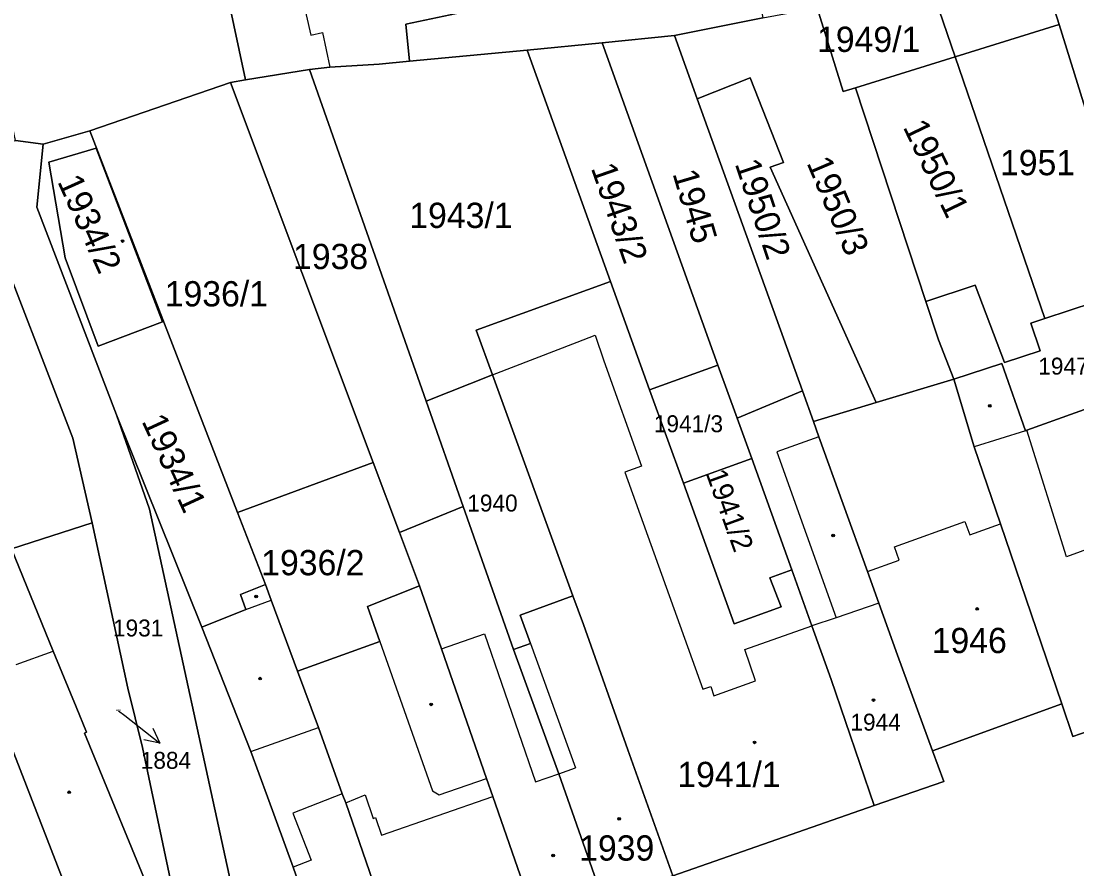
# Model space of a CAD drawing. Extents: x -596233 to -595156, y -1161235 to -1159375.
# Drawn here: x -595806.5 to -595735.4, y -1161105.5 to -1161048.4 of the extents above; entities that cross this region are included whole.
import ezdxf

# ---------------------------------------------------------------- set-up
doc = ezdxf.new("R2010")
doc.units = 0
for name, color, linetype in [('KN_CAR_KR', 7, 'Continuous'), ('KN_KULTURY', 7, 'Continuous'), ('KN_PARC_CIS_POM', 7, 'Continuous'), ('KN_PARC_CIS_POZ', 7, 'Continuous'), ('KN_PARC_CIS_STAV', 7, 'Continuous'), ('KN_PARC_PLOCHA', 7, 'Continuous'), ('PARC_C_SIPKA', 7, 'Continuous'), ('parcely_l', 7, 'Continuous')]:
    doc.layers.add(name, color=color, linetype=linetype)

msp = doc.modelspace()

# ---------------------------------------------------------------- linework, layer by layer
at = {"layer": 'KN_CAR_KR'}
for points in [[(-595788.64, -1161041.96), (-595786.95, -1161049.32)], [(-595786.95, -1161049.32), (-595786.17, -1161049.15)], [(-595786.17, -1161049.15), (-595785.67, -1161051.48)], [(-595774.72, -1161072.19), (-595769.01, -1161069.99)], [(-595769.01, -1161069.99), (-595767.8, -1161069.52)], [(-595767.8, -1161069.52), (-595767.22, -1161071.25)], [(-595767.22, -1161071.25), (-595764.67, -1161078.34)], [(-595752.73, -1161076.37), (-595755.57, -1161077.39)], [(-595738.83, -1161075.96), (-595742.28, -1161077.04)], [(-595736.05, -1161084.45), (-595738.73, -1161075.93)], [(-595755.57, -1161077.39), (-595751.57, -1161088.55)], [(-595764.67, -1161078.34), (-595765.8, -1161078.74)], [(-595765.8, -1161078.74), (-595760.56, -1161093.36)], [(-595747.65, -1161083.78), (-595742.9, -1161082.08)], [(-595742.9, -1161082.08), (-595742.58, -1161082.97)], [(-595729.38, -1161082.01), (-595736.05, -1161084.45)], [(-595742.58, -1161082.97), (-595740.51, -1161082.23)], [(-595747.33, -1161084.68), (-595747.65, -1161083.78)], [(-595749.45, -1161085.44), (-595747.33, -1161084.68)], [(-595791.33, -1161087.99), (-595789.62, -1161087.36)], [(-595748.7, -1161087.56), (-595751.57, -1161088.55)], [(-595757.71, -1161090.69), (-595753.2, -1161089.1)], [(-595751.57, -1161088.55), (-595753.2, -1161089.1)], [(-595778.14, -1161090.64), (-595775.26, -1161089.63)], [(-595775.26, -1161089.63), (-595771.81, -1161099.59)], [(-595782.3, -1161090.16), (-595778.76, -1161100.2)], [(-595772.16, -1161090.28), (-595769.12, -1161098.66)], [(-595806.8, -1161091.7), (-595804.29, -1161090.8)], [(-595757, -1161092.79), (-595757.71, -1161090.69)], [(-595760.56, -1161093.36), (-595760.02, -1161093.17)], [(-595760.02, -1161093.17), (-595759.8, -1161093.81)], [(-595759.8, -1161093.81), (-595757, -1161092.79)], [(-595790.99, -1161097.55), (-595786.43, -1161095.95)], [(-595771.81, -1161099.59), (-595770.25, -1161099.05)], [(-595770.25, -1161099.05), (-595769.12, -1161098.66)], [(-595778.3, -1161100.48), (-595775.11, -1161099.37)], [(-595784.83, -1161100.41), (-595788.16, -1161101.71)], [(-595784.59, -1161101), (-595783.29, -1161100.48)], [(-595783.29, -1161100.48), (-595782.76, -1161102.06)], [(-595778.76, -1161100.2), (-595778.3, -1161100.48)], [(-595782.19, -1161103.19), (-595774.69, -1161100.59)], [(-595788.16, -1161101.71), (-595786.93, -1161104.88)], [(-595782.76, -1161102.06), (-595782.59, -1161102)], [(-595782.59, -1161102), (-595782.19, -1161103.19)], [(-595786.93, -1161104.88), (-595788.14, -1161105.35)]]:
    msp.add_lwpolyline(points, dxfattribs=at)
at = {"layer": 'KN_KULTURY'}
for centre, radius in [((-595799.62, -1161063.19), 0.09), ((-595799.62, -1161063.19), 0.0398), ((-595741.23, -1161074.29), 0.09), ((-595741.23, -1161074.29), 0.0398), ((-595751.77, -1161083.02), 0.09), ((-595751.77, -1161083.02), 0.0398), ((-595790.63, -1161087.12), 0.09), ((-595790.63, -1161087.12), 0.0398), ((-595742.07, -1161087.96), 0.09), ((-595742.07, -1161087.96), 0.0398), ((-595790.37, -1161092.65), 0.09), ((-595790.37, -1161092.65), 0.0398), ((-595749.06, -1161094.09), 0.09), ((-595749.06, -1161094.09), 0.0398), ((-595778.84, -1161094.38), 0.09), ((-595778.84, -1161094.38), 0.0398), ((-595757.06, -1161096.94), 0.09), ((-595757.06, -1161096.94), 0.0398), ((-595803.22, -1161100.3), 0.09), ((-595803.22, -1161100.3), 0.0398), ((-595766.19, -1161102.09), 0.09), ((-595766.19, -1161102.09), 0.0398), ((-595770.63, -1161104.55), 0.09), ((-595770.63, -1161104.55), 0.0398)]:
    msp.add_circle(centre, radius, dxfattribs=at)
at = {"layer": 'KN_PARC_PLOCHA'}
for points in [[(-595800.84, -1161007.79), (-595797.39, -1161024.01), (-595795.85, -1161031.24), (-595794.6, -1161037.1), (-595793.35, -1161042.96), (-595791.35, -1161052.34), (-595792.36, -1161052.52), (-595801.84, -1161055.76), (-595804.98, -1161056.66), (-595806.83, -1161056.42), (-595808.05, -1161050.74), (-595809.17, -1161045.43), (-595810.29, -1161040.1), (-595811.82, -1161032.84), (-595812.42, -1161029.86), (-595813.02, -1161026.89), (-595816.25, -1161010.92)], [(-595807.91, -1161121.82), (-595798.85, -1161118.51), (-595794.32, -1161116.86), (-595790.25, -1161115.45), (-595785.2, -1161113.74), (-595780.74, -1161112.21), (-595771.72, -1161109.12), (-595767.26, -1161107.57), (-595762.56, -1161105.93), (-595749.01, -1161101.2), (-595744.33, -1161099.57), (-595745.08, -1161097.51), (-595736.38, -1161094.34), (-595735.63, -1161096.54), (-595722.22, -1161091.87)]]:
    msp.add_lwpolyline(points, dxfattribs=at)
for points in [[(-595756.52, -1161048.16), (-595762.45, -1161049.35), (-595767.32, -1161049.84), (-595772.39, -1161050.35), (-595780.31, -1161051.09), (-595780.54, -1161048.59), (-595774.15, -1161047.25), (-595769.47, -1161046.26), (-595771.18, -1161038.24), (-595759.1, -1161035.67)], [(-595780.31, -1161051.09), (-595782.34, -1161051.28), (-595785.67, -1161051.48), (-595787.03, -1161051.65), (-595791.35, -1161052.34), (-595793.35, -1161042.96), (-595788.64, -1161041.96), (-595778.17, -1161039.73), (-595776.02, -1161039.27), (-595775.04, -1161039.06), (-595771.18, -1161038.24), (-595769.47, -1161046.26), (-595774.15, -1161047.25), (-595780.54, -1161048.59)], [(-595726.93, -1161054.01), (-595734.08, -1161056.56), (-595736.56, -1161048.61), (-595738.25, -1161043.22), (-595735.43, -1161042.27), (-595731.29, -1161041.19), (-595730.52, -1161043.46)], [(-595736.56, -1161048.61), (-595743.56, -1161050.78), (-595745.45, -1161045.26), (-595742.24, -1161044.34), (-595738.25, -1161043.22)], [(-595743.56, -1161050.78), (-595750.27, -1161052.87), (-595751.09, -1161053.12), (-595752.84, -1161047.48), (-595752.12, -1161047.27), (-595749.08, -1161046.3), (-595745.45, -1161045.26)], [(-595750.27, -1161052.87), (-595745.53, -1161067.27), (-595744.68, -1161069.83), (-595743.64, -1161072.48), (-595748.88, -1161074.06), (-595756.02, -1161058.22), (-595755.12, -1161057.9), (-595757.37, -1161052.2), (-595760.92, -1161053.61), (-595762.45, -1161049.35), (-595756.52, -1161048.16), (-595752.84, -1161047.48), (-595751.09, -1161053.12)], [(-595734.08, -1161056.56), (-595733.05, -1161059.84), (-595730.97, -1161066.25), (-595737.52, -1161068.41), (-595743.56, -1161050.78), (-595736.56, -1161048.61)], [(-595760.92, -1161053.61), (-595753.84, -1161073.28), (-595758.23, -1161075.11), (-595759.53, -1161071.54), (-595767.32, -1161049.84), (-595762.45, -1161049.35)], [(-595759.53, -1161071.54), (-595764.13, -1161073.2), (-595766.76, -1161065.92), (-595772.39, -1161050.35), (-595767.32, -1161049.84)], [(-595766.76, -1161065.92), (-595775.81, -1161069.19), (-595774.72, -1161072.19), (-595779.18, -1161073.96), (-595787.03, -1161051.65), (-595785.67, -1161051.48), (-595782.34, -1161051.28), (-595780.31, -1161051.09), (-595772.39, -1161050.35)], [(-595737.52, -1161068.41), (-595738.45, -1161068.71), (-595737.84, -1161070.58), (-595740.24, -1161071.36), (-595742.2, -1161066.17), (-595745.53, -1161067.27), (-595750.27, -1161052.87), (-595743.56, -1161050.78)], [(-595779.18, -1161073.96), (-595776.68, -1161081.06), (-595780.97, -1161082.81), (-595782.74, -1161078.1), (-595792.36, -1161052.52), (-595791.35, -1161052.34), (-595787.03, -1161051.65)], [(-595748.88, -1161074.06), (-595753.1, -1161075.34), (-595753.84, -1161073.28), (-595760.92, -1161053.61), (-595757.37, -1161052.2), (-595755.12, -1161057.9), (-595756.02, -1161058.22)], [(-595782.74, -1161078.1), (-595791.89, -1161081.47), (-595801.84, -1161055.76), (-595792.36, -1161052.52)], [(-595791.89, -1161081.47), (-595790.01, -1161086.32), (-595791.69, -1161086.99), (-595791.33, -1161087.99), (-595794.28, -1161089.18), (-595800.03, -1161074.9), (-595805.4, -1161060.91), (-595804.98, -1161056.66), (-595801.84, -1161055.76)], [(-595804.98, -1161056.66), (-595805.4, -1161060.91), (-595800.03, -1161074.9), (-595797.81, -1161081.24), (-595792.22, -1161106.92), (-595791.69, -1161109.49), (-595790.8, -1161112.68), (-595790.25, -1161115.45), (-595794.32, -1161116.86), (-595795.4, -1161113.74), (-595794.67, -1161113.51), (-595794.99, -1161112.49), (-595794.8, -1161112.43), (-595795.45, -1161110.68), (-595798.28, -1161097.28), (-595799.26, -1161093.3), (-595801.67, -1161082.16), (-595802.97, -1161076.46), (-595808.63, -1161061.82), (-595808.8, -1161058.15), (-595808.86, -1161056.87), (-595806.83, -1161056.42)], [(-595796.93, -1161068.63), (-595801.41, -1161056.93), (-595804.58, -1161057.87), (-595803.49, -1161064.33), (-595801.27, -1161070.26)], [(-595796.93, -1161068.63), (-595801.27, -1161070.26), (-595803.49, -1161064.33), (-595804.58, -1161057.87), (-595801.41, -1161056.93)], [(-595801.67, -1161082.16), (-595807.1, -1161083.92), (-595816.53, -1161060.79), (-595808.8, -1161058.15), (-595808.63, -1161061.82), (-595802.97, -1161076.46)], [(-595764.13, -1161073.2), (-595761.86, -1161079.48), (-595758.44, -1161088.96), (-595755.28, -1161087.82), (-595756.04, -1161085.86), (-595754.56, -1161085.33), (-595753.2, -1161089.1), (-595751.9, -1161092.71), (-595749.01, -1161101.2), (-595762.56, -1161105.93), (-595765.6, -1161097.44), (-595768.59, -1161089.01), (-595769.3, -1161087.07), (-595774.72, -1161072.19), (-595775.81, -1161069.19), (-595766.76, -1161065.92)], [(-595737.52, -1161068.41), (-595730.97, -1161066.25), (-595728.96, -1161072.47), (-595732.23, -1161073.59), (-595738.73, -1161075.93), (-595738.83, -1161075.96), (-595740.41, -1161071.44), (-595743.64, -1161072.48), (-595744.68, -1161069.83), (-595745.53, -1161067.27), (-595742.2, -1161066.17), (-595740.24, -1161071.36), (-595737.84, -1161070.58), (-595738.45, -1161068.71)], [(-595758.23, -1161075.11), (-595757.25, -1161077.84), (-595761.86, -1161079.48), (-595764.13, -1161073.2), (-595759.53, -1161071.54)], [(-595728.96, -1161072.47), (-595722.22, -1161091.87), (-595735.63, -1161096.54), (-595736.38, -1161094.34), (-595740.51, -1161082.23), (-595742.28, -1161077.04), (-595743.64, -1161072.48), (-595740.41, -1161071.44), (-595738.83, -1161075.96), (-595738.73, -1161075.93), (-595732.23, -1161073.59)], [(-595769.3, -1161087.07), (-595772.85, -1161088.37), (-595772.16, -1161090.28), (-595773.3, -1161090.68), (-595776.68, -1161081.06), (-595779.18, -1161073.96), (-595774.72, -1161072.19)], [(-595736.38, -1161094.34), (-595745.08, -1161097.51), (-595747.44, -1161091.08), (-595748.7, -1161087.56), (-595749.45, -1161085.44), (-595752.73, -1161076.37), (-595753.1, -1161075.34), (-595748.88, -1161074.06), (-595743.64, -1161072.48), (-595742.28, -1161077.04), (-595740.51, -1161082.23)], [(-595753.1, -1161075.34), (-595752.73, -1161076.37), (-595749.45, -1161085.44), (-595748.7, -1161087.56), (-595747.44, -1161091.08), (-595745.08, -1161097.51), (-595744.33, -1161099.57), (-595749.01, -1161101.2), (-595751.9, -1161092.71), (-595753.2, -1161089.1), (-595754.56, -1161085.33), (-595757.25, -1161077.84), (-595758.23, -1161075.11), (-595753.84, -1161073.28)], [(-595794.28, -1161089.18), (-595790.99, -1161097.55), (-595789.87, -1161100.6), (-595788.14, -1161105.35), (-595786.04, -1161111.35), (-595790.8, -1161112.68), (-595791.69, -1161109.49), (-595792.22, -1161106.92), (-595797.81, -1161081.24), (-595800.03, -1161074.9)], [(-595780.97, -1161082.81), (-595779.62, -1161086.41), (-595783.13, -1161087.79), (-595782.3, -1161090.16), (-595787.85, -1161092.14), (-595789.62, -1161087.36), (-595790.01, -1161086.32), (-595791.89, -1161081.47), (-595782.74, -1161078.1)], [(-595754.56, -1161085.33), (-595756.04, -1161085.86), (-595755.28, -1161087.82), (-595758.44, -1161088.96), (-595761.86, -1161079.48), (-595757.25, -1161077.84)], [(-595773.3, -1161090.68), (-595770.25, -1161099.05), (-595767.26, -1161107.57), (-595771.72, -1161109.12), (-595774.69, -1161100.59), (-595775.11, -1161099.37), (-595778.14, -1161090.64), (-595779.62, -1161086.41), (-595780.97, -1161082.81), (-595776.68, -1161081.06)], [(-595795.4, -1161113.74), (-595797.32, -1161108.16), (-595802.2, -1161096.32), (-595802.06, -1161096.26), (-595802.76, -1161094.55), (-595803.14, -1161093.62), (-595804.29, -1161090.8), (-595807.1, -1161083.92), (-595801.67, -1161082.16), (-595799.26, -1161093.3), (-595798.28, -1161097.28), (-595795.45, -1161110.68), (-595794.8, -1161112.43), (-595794.99, -1161112.49), (-595794.67, -1161113.51)], [(-595795.4, -1161113.74), (-595794.32, -1161116.86), (-595798.85, -1161118.51), (-595802.19, -1161109.94), (-595808.36, -1161094.07), (-595809.01, -1161092.5), (-595810.6, -1161088.67), (-595811.92, -1161085.48), (-595807.1, -1161083.92), (-595804.29, -1161090.8), (-595803.14, -1161093.62), (-595802.76, -1161094.55), (-595802.06, -1161096.26), (-595802.2, -1161096.32), (-595797.32, -1161108.16)], [(-595787.85, -1161092.14), (-595786.43, -1161095.95), (-595784.83, -1161100.41), (-595784.59, -1161101), (-595780.74, -1161112.21), (-595785.2, -1161113.74), (-595786.04, -1161111.35), (-595788.14, -1161105.35), (-595789.87, -1161100.6), (-595790.99, -1161097.55), (-595794.28, -1161089.18), (-595791.33, -1161087.99), (-595791.69, -1161086.99), (-595790.01, -1161086.32), (-595789.62, -1161087.36)], [(-595771.72, -1161109.12), (-595780.74, -1161112.21), (-595784.59, -1161101), (-595784.83, -1161100.41), (-595786.43, -1161095.95), (-595787.85, -1161092.14), (-595782.3, -1161090.16), (-595783.13, -1161087.79), (-595779.62, -1161086.41), (-595778.14, -1161090.64), (-595775.11, -1161099.37), (-595774.69, -1161100.59)], [(-595762.56, -1161105.93), (-595767.26, -1161107.57), (-595770.25, -1161099.05), (-595773.3, -1161090.68), (-595772.16, -1161090.28), (-595772.85, -1161088.37), (-595769.3, -1161087.07), (-595768.59, -1161089.01), (-595765.6, -1161097.44)], [(-595798.85, -1161118.51), (-595807.91, -1161121.82), (-595811.33, -1161113.28), (-595812.14, -1161111.26), (-595813.67, -1161107.43), (-595815.57, -1161102.7), (-595817.06, -1161097.88), (-595812.99, -1161096.1), (-595811.89, -1161095.61), (-595808.36, -1161094.07), (-595802.19, -1161109.94)]]:
    msp.add_lwpolyline(points, close=True, dxfattribs=at)
at = {"layer": 'PARC_C_SIPKA'}
for points in [[(-595799.89, -1161094.82), (-595799.47, -1161095.14), (-595797.1052, -1161096.9859)], [(-595797.5858, -1161095.9765), (-595797.1052, -1161096.9859), (-595798.2011, -1161096.7648)]]:
    msp.add_lwpolyline(points, dxfattribs=at)
at = {"layer": 'parcely_l'}
for points in [[(-595780.31, -1161051.09), (-595780.54, -1161048.59), (-595774.15, -1161047.25), (-595769.47, -1161046.26), (-595771.18, -1161038.24)], [(-595793.35, -1161042.96), (-595791.35, -1161052.34)], [(-595738.25, -1161043.22), (-595736.56, -1161048.61)], [(-595745.45, -1161045.26), (-595743.56, -1161050.78)], [(-595752.84, -1161047.48), (-595751.09, -1161053.12), (-595750.27, -1161052.87)], [(-595756.52, -1161048.16), (-595762.45, -1161049.35)], [(-595743.56, -1161050.78), (-595736.56, -1161048.61)], [(-595736.56, -1161048.61), (-595734.08, -1161056.56)], [(-595767.32, -1161049.84), (-595762.45, -1161049.35)], [(-595762.45, -1161049.35), (-595760.92, -1161053.61)], [(-595767.32, -1161049.84), (-595772.39, -1161050.35)], [(-595759.53, -1161071.54), (-595767.32, -1161049.84)], [(-595772.39, -1161050.35), (-595780.31, -1161051.09)], [(-595772.39, -1161050.35), (-595766.76, -1161065.92)], [(-595750.27, -1161052.87), (-595743.56, -1161050.78)], [(-595743.56, -1161050.78), (-595737.52, -1161068.41)], [(-595787.03, -1161051.65), (-595785.67, -1161051.48), (-595782.34, -1161051.28), (-595780.31, -1161051.09)], [(-595791.35, -1161052.34), (-595787.03, -1161051.65)], [(-595779.18, -1161073.96), (-595787.03, -1161051.65)], [(-595748.88, -1161074.06), (-595756.02, -1161058.22), (-595755.12, -1161057.9), (-595757.37, -1161052.2), (-595760.92, -1161053.61)], [(-595792.36, -1161052.52), (-595801.84, -1161055.76)], [(-595791.35, -1161052.34), (-595792.36, -1161052.52)], [(-595782.74, -1161078.1), (-595792.36, -1161052.52)], [(-595745.53, -1161067.27), (-595750.27, -1161052.87)], [(-595760.92, -1161053.61), (-595753.84, -1161073.28)], [(-595801.84, -1161055.76), (-595804.98, -1161056.66)], [(-595801.84, -1161055.76), (-595791.89, -1161081.47)], [(-595804.98, -1161056.66), (-595806.83, -1161056.42)], [(-595804.98, -1161056.66), (-595805.4, -1161060.91), (-595800.03, -1161074.9)], [(-595796.93, -1161068.63), (-595801.27, -1161070.26), (-595803.49, -1161064.33), (-595804.58, -1161057.87), (-595801.41, -1161056.93), (-595796.93, -1161068.63)], [(-595801.67, -1161082.16), (-595802.97, -1161076.46), (-595808.63, -1161061.82), (-595808.8, -1161058.15)], [(-595774.72, -1161072.19), (-595775.81, -1161069.19), (-595766.76, -1161065.92)], [(-595766.76, -1161065.92), (-595764.13, -1161073.2)], [(-595737.52, -1161068.41), (-595738.45, -1161068.71), (-595737.84, -1161070.58), (-595740.24, -1161071.36), (-595742.2, -1161066.17), (-595745.53, -1161067.27)], [(-595737.52, -1161068.41), (-595730.97, -1161066.25)], [(-595743.64, -1161072.48), (-595744.68, -1161069.83), (-595745.53, -1161067.27)], [(-595764.13, -1161073.2), (-595759.53, -1161071.54)], [(-595758.23, -1161075.11), (-595759.53, -1161071.54)], [(-595728.96, -1161072.47), (-595732.23, -1161073.59), (-595738.73, -1161075.93), (-595738.83, -1161075.96), (-595740.41, -1161071.44), (-595743.64, -1161072.48)], [(-595779.18, -1161073.96), (-595774.72, -1161072.19)], [(-595774.72, -1161072.19), (-595769.3, -1161087.07)], [(-595743.64, -1161072.48), (-595748.88, -1161074.06)], [(-595736.38, -1161094.34), (-595740.51, -1161082.23), (-595742.28, -1161077.04), (-595743.64, -1161072.48)], [(-595764.13, -1161073.2), (-595761.86, -1161079.48)], [(-595753.84, -1161073.28), (-595758.23, -1161075.11)], [(-595753.84, -1161073.28), (-595753.1, -1161075.34)], [(-595776.68, -1161081.06), (-595779.18, -1161073.96)], [(-595753.1, -1161075.34), (-595748.88, -1161074.06)], [(-595800.03, -1161074.9), (-595797.81, -1161081.24), (-595792.22, -1161106.92), (-595791.69, -1161109.49), (-595790.8, -1161112.68)], [(-595800.03, -1161074.9), (-595794.28, -1161089.18)], [(-595757.25, -1161077.84), (-595758.23, -1161075.11)], [(-595753.1, -1161075.34), (-595752.73, -1161076.37), (-595749.45, -1161085.44), (-595748.7, -1161087.56), (-595747.44, -1161091.08), (-595745.08, -1161097.51)], [(-595791.89, -1161081.47), (-595782.74, -1161078.1)], [(-595782.74, -1161078.1), (-595780.97, -1161082.81)], [(-595761.86, -1161079.48), (-595757.25, -1161077.84)], [(-595757.25, -1161077.84), (-595754.56, -1161085.33)], [(-595754.56, -1161085.33), (-595756.04, -1161085.86), (-595755.28, -1161087.82), (-595758.44, -1161088.96), (-595761.86, -1161079.48)], [(-595780.97, -1161082.81), (-595776.68, -1161081.06)], [(-595773.3, -1161090.68), (-595776.68, -1161081.06)], [(-595791.89, -1161081.47), (-595790.01, -1161086.32)], [(-595801.67, -1161082.16), (-595807.1, -1161083.92)], [(-595795.4, -1161113.74), (-595794.67, -1161113.51), (-595794.99, -1161112.49), (-595794.8, -1161112.43), (-595795.45, -1161110.68), (-595798.28, -1161097.28), (-595799.26, -1161093.3), (-595801.67, -1161082.16)], [(-595779.62, -1161086.41), (-595780.97, -1161082.81)], [(-595807.1, -1161083.92), (-595804.29, -1161090.8), (-595803.14, -1161093.62), (-595802.76, -1161094.55), (-595802.06, -1161096.26), (-595802.2, -1161096.32), (-595797.32, -1161108.16), (-595795.4, -1161113.74)], [(-595754.56, -1161085.33), (-595753.2, -1161089.1), (-595751.9, -1161092.71), (-595749.01, -1161101.2)], [(-595790.01, -1161086.32), (-595791.69, -1161086.99), (-595791.33, -1161087.99), (-595794.28, -1161089.18)], [(-595787.85, -1161092.14), (-595789.62, -1161087.36), (-595790.01, -1161086.32)], [(-595787.85, -1161092.14), (-595782.3, -1161090.16), (-595783.13, -1161087.79), (-595779.62, -1161086.41)], [(-595771.72, -1161109.12), (-595774.69, -1161100.59), (-595775.11, -1161099.37), (-595778.14, -1161090.64), (-595779.62, -1161086.41)], [(-595769.3, -1161087.07), (-595772.85, -1161088.37), (-595772.16, -1161090.28), (-595773.3, -1161090.68)], [(-595762.56, -1161105.93), (-595765.6, -1161097.44), (-595768.59, -1161089.01), (-595769.3, -1161087.07)], [(-595794.28, -1161089.18), (-595790.99, -1161097.55), (-595789.87, -1161100.6), (-595788.14, -1161105.35), (-595786.04, -1161111.35)], [(-595773.3, -1161090.68), (-595770.25, -1161099.05), (-595767.26, -1161107.57)], [(-595736.38, -1161094.34), (-595735.63, -1161096.54), (-595722.22, -1161091.87)], [(-595780.74, -1161112.21), (-595784.59, -1161101), (-595784.83, -1161100.41), (-595786.43, -1161095.95), (-595787.85, -1161092.14)], [(-595808.36, -1161094.07), (-595802.19, -1161109.94), (-595798.85, -1161118.51)], [(-595745.08, -1161097.51), (-595736.38, -1161094.34)], [(-595749.01, -1161101.2), (-595744.33, -1161099.57), (-595745.08, -1161097.51)], [(-595749.01, -1161101.2), (-595762.56, -1161105.93)]]:
    msp.add_lwpolyline(points, dxfattribs=at)

# ---------------------------------------------------------------- texts
at = {"layer": 'KN_PARC_CIS_POM'}
msp.add_text('1884', height=0.1, dxfattribs=at).set_placement((-595800.0733, -1161094.82))
at = {"layer": 'KN_PARC_CIS_POZ'}
for s, height, p in [('1949/1', 1.7, (-595752.8566, -1161050.46)), ('1951', 1.7, (-595740.5366, -1161058.76)), ('1943/1', 1.7, (-595780.3166, -1161062.31)), ('1938', 1.7, (-595788.1466, -1161065.08)), ('1936/1', 1.7, (-595796.7866, -1161067.59)), ('1947/2', 1.14, (-595737.96, -1161072.18)), ('1941/3', 1.14, (-595763.85, -1161076.06)), ('1940', 1.14, (-595776.41, -1161081.4)), ('1936/2', 1.7, (-595790.2866, -1161085.69)), ('1931', 1.14, (-595800.27, -1161089.81)), ('1884', 1.14, (-595798.4, -1161098.72))]:
    msp.add_text(s, height=height, dxfattribs=at).set_placement(p)
for s, height, rotation, p in [('1950/1', 1.7, 295.718951, (-595747.1002, -1161055.5105)), ('1950/2', 1.7, 288.478292, (-595758.4066, -1161057.9817)), ('1950/3', 1.7, 292.993543, (-595753.5815, -1161057.9261)), ('1943/2', 1.7, 289.168951, (-595768.1016, -1161058.2704)), ('1945', 1.7, 286.425488, (-595762.6013, -1161058.6406)), ('1934/1', 1.7, 294.699736, (-595798.3671, -1161075.3108)), ('1941/2', 1.4, 289.842312, (-595760.3564, -1161078.8489))]:
    msp.add_text(s, height=height, rotation=rotation, dxfattribs=at).set_placement(p)
at = {"layer": 'KN_PARC_CIS_STAV'}
msp.add_text('1934/2', height=1.7, rotation=294.300105, dxfattribs=at).set_placement((-595804.0379, -1161059.1815))
for s, height, p in [('1946', 1.7, (-595745.1366, -1161090.93)), ('1944', 1.14, (-595750.61, -1161096.15)), ('1941/1', 1.7, (-595762.2666, -1161099.95)), ('1939', 1.7, (-595768.8766, -1161104.9))]:
    msp.add_text(s, height=height, dxfattribs=at).set_placement(p)

doc.saveas('drawing.dxf')
